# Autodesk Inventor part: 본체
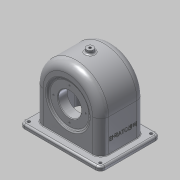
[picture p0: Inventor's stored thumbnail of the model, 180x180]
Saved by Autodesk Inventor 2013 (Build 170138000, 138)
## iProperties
Created: 2016-01
Part Number: 본체
Material: 알루미늄 6061
Document SubType Name: Modeling
Designer: dgall
Mass: 809.516 g
Surface Area: 999.209 cm^2
Volume: 298.714 cm^3
Density: 2.71 g/cm^3
Author: dgall
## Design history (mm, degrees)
sketch "스케치1"
  geometry: L1 (57, 0)-(57, -64); L2 (-57, 0)-(-57, -64); L3 (57, -64)-(-57, -64); A1 r 57 centre (0, 0) between (57, 0) and (-57, 0); 1 further point
  constraints: 6 end point, 2 parallel, 2 point on circle, 2 tangent, 1 centre point, 1 coincident, 1 perpendicular, 1 vertical
  dimensions: "d0" = 114 diameter of A1; "d2" = 64 vertical distance of L1.end point (0, 0)
extrude "돌출1" new body sketch "스케치1" distance "d3" = 77; taper "d4" = 0 deg
feature "쉘1" dims "d5" = 6
sketch "스케치2"
  geometry: L1 (-51, -64)-(-51, 0) reference; L2 (51, -64)-(-51, -64) reference; L3 (51, 0)-(51, -64) reference; A1 r 51 centre (0, 0) between (51, 0) and (-51, 0) reference
extrude "돌출2" cut sketch "스케치2" distance "d6" = 1; taper "d7" = 0 deg
sketch "스케치3"
  geometry: L1 (51, 0)-(51, 64) reference; L2 (-51, 64)-(51, 64) reference; L3 (-51, 64)-(-51, 0) reference; A1 r 51 centre (0, 0) between (-51, 0) and (51, 0) reference
extrude "돌출3" cut sketch "스케치3" distance "d8" = 1; taper "d9" = 0 deg
fillet "모깎기1" dims "d10" = 14, "d11" = 9
sketch "스케치4"
  geometry: L1 (-14, 14)-(-14, 63) reference; L2 (0, 0)-(86, 0) reference; L3 (100, 14)-(100, 63) reference; L4 (0, 77)-(86, 77) reference; L5 (-27, 90.5)-(113, 90.5); L6 (113, 90.5)-(113, -13.5); L7 (113, -13.5)-(-27, -13.5); L8 (-27, -13.5)-(-27, 90.5); L9 (-14, 38.5)-(100, 38.5); A1 r 14 centre (0, 63) between (0, 77) and (-14, 63) reference; A2 r 14 centre (0, 14) between (-14, 14) and (0, 0) reference; A3 r 14 centre (86, 14) between (86, 0) and (100, 14) reference; A4 r 14 centre (86, 63) between (100, 63) and (86, 77) reference; 1 further point
  constraints: 10 end point, 2 midpoint, 2 parallel, 1 horizontal, 1 perpendicular
  dimensions: "d12" = 140 distance between parallel lines of L6 L8; "d14" = 70 distance from line of point (43, 0) L8; "d15" = 104 distance between parallel lines of L7 L5; "d16" = 52 distance between parallel lines of L9 L5
extrude "돌출4" join sketch "스케치4" distance "d17" = 7; taper "d18" = 0 deg
fillet "모깎기2" dims "d19" = 8
sketch "스케치5"
  geometry: C1 r 2.5 at (-105, 82.5); C2 r 2.5 at (19, 82.5); C3 r 2.5 at (-105, -5.5); C4 r 2.5 at (19, -5.5); A1 r 8 centre (-105, 82.5) between (-105, 90.5) and (-113, 82.5) reference; A2 r 8 centre (-105, -5.5) between (-113, -5.5) and (-105, -13.5) reference; A3 r 8 centre (19, -5.5) between (19, -13.5) and (27, -5.5) reference; A4 r 8 centre (19, 82.5) between (27, 82.5) and (19, 90.5) reference; 1 further point
  constraints: 4 centre point, 4 coincident, 3 equal radius
  dimensions: "d20" = 5 diameter of C1
extrude "돌출5" cut sketch "스케치5" distance "d22" = 7; taper "d23" = 0 deg
sketch "스케치6"
  geometry: L1 (-62, 57)-(-62, 64) reference; L2 (62, 57)-(-62, 57) reference; L3 (62, 64)-(62, 57) reference; L4 (62, 64)-(-62, 64) reference; C1 r 31 at (0, 4); A1 r 43 centre (0, 0) between (-43, 0) and (43, 0) reference
  constraints: 1 centre point, 1 vertical alignment
  dimensions: "d24" = 60 distance from line of L4 C1.centre; "d25" = 62 diameter of C1
extrude "돌출6" join sketch "스케치6" distance "d26" = 10; taper "d27" = 0 deg
sketch "스케치7"
  geometry: C1 r 31 at (0, 0) reference; C2 r 20 at (0, 0); 1 further point
  constraints: 1 centre point, 1 coincident
  dimensions: "d28" = 40 diameter of C2
extrude "돌출7" cut sketch "스케치7" distance "d30" = 20.75; taper "d31" = 0 deg
sketch "스케치8"
  geometry: L1 (5, 42)-(5, 0) reference; L2 (5, 0)-(5, -64) reference; L3 (0, 0)-(0, 43) reference; L4 (0, -57)-(0, 0) reference; L5 (63, -64)-(14, -64) reference; L6 (0, -4)-(54.607, -4); L7 (5, -4)-(19, -4); L8 (19, -4)-(19, 24); L9 (19, 24)-(5, 35.747)
  constraints: 8 end point, 5 point on line, 1 parallel, 1 perpendicular
  dimensions: "d32" = 60 distance between parallel lines of L5 L6; "d33" = 28 distance from line of L6 L8.end; "d34" = 50 deg angle of L9 L8; "d36" = 14 distance between parallel lines of L8 L1
revolve "회전1" sketch "스케치8" stored, may be unused: angle "d37" = 90 deg
sketch "스케치11"
  geometry: L1 (5, 35.747)-(19, 24) reference; L2 (0, 33.416)-(3, 30.899); L3 (0, 0)-(0, 43) reference; L4 (0, -57)-(0, 0) reference; L5 (3, 30.899)-(3, -4); L6 (19, -32)-(19, 24) reference; L7 (19, -4)-(0, -4); L8 (0, 33.416)-(0, -4); L9 (3, -4)-(0, -4); L10 (63, -64)-(14, -64) reference
  constraints: 10 end point, 3 point on line, 2 collinear, 2 perpendicular, 1 midpoint, 1 parallel
  dimensions: "d45" = 5 distance between parallel lines of L1 L2; "d46" = 3 distance between parallel lines of L5 L3
revolve "회전3" sketch "스케치11" stored, may be unused: angle "d47" = 90 deg
sketch "스케치12"
  geometry: C1 r 34.899 at (0, 0) reference; C2 r 20 at (0, 0); 1 further point
  constraints: 1 centre point, 1 coincident
  dimensions: "d48" = 40 diameter of C2
extrude "돌출9" cut sketch "스케치12" distance "d50" = 20.75; taper "d51" = 0 deg
chamfer "모따기1" distance "d52" = 1; stored, may be unused: second distance "d53" = 2, angle "d54" = 45 deg
fillet "모깎기3" dims "d55" = 3
sketch "스케치13" dims "d56" = 48
  geometry: L1 (0, 0)-(0, -24); C1 r 21 at (0, 0) reference; C2 r 1.986 at (0, -24); C3 r 1.986 at (24, 0); C4 r 1.986 at (0, 24); C5 r 1.986 at (-24, 0); 1 further point
  constraints: 4 centre point, 2 coincident, 2 end point, 1 vertical, 1 vertical alignment, 11 other
  dimensions: "d60" = 360 deg dimension on L1.start C2.centre (derived)
hole "구멍1" sketch "스케치13" at (24, 0), (0, 24), (-24, 0), (0, -24) diameter "d62" = 2.459; stored, may be unused: countersink angle "d66" = 90 deg, drill point angle "d68" = 118 deg; dims "d63" = 6, "d64" = 4, "d65" = 2, "d67" = 8
sketch "스케치14" dims "d69" = 56
  geometry: L1 (0, 0)-(0, 28); C1 r 33.5 at (0, 0) reference; C2 r 2.705 at (0, 28); C3 r 2.705 at (-28, 0); C4 r 2.705 at (0, -28); C5 r 2.705 at (28, 0); 1 further point
  constraints: 4 centre point, 2 coincident, 2 end point, 1 vertical, 1 vertical alignment, 11 other
  dimensions: "d73" = 360 deg dimension on L1.start C2.centre (derived)
hole "구멍2" sketch "스케치14" at (0, 28), (28, 0), (0, -28), (-28, 0) diameter "d75" = 2.459; stored, may be unused: countersink angle "d79" = 90 deg, drill point angle "d81" = 118 deg; dims "d76" = 7, "d77" = 4, "d78" = 2, "d80" = 9
node "작업 평면2"
  node "작업 평면1"
sketch "스케치15"
  geometry: L1 (-43, 77)-(43, 77) reference; L2 (43, 0)-(-43, 0) reference; C1 r 6 at (0, 38.5); 2 further points
  constraints: 1 centre point, 1 midpoint, 1 vertical alignment
  dimensions: "d83" = 12 diameter of C1; "d85" = 38.5 distance from line of C1.centre L1
extrude "돌출10" join sketch "스케치15" stored distance "d86" = 20.75; taper "d87" = 0 deg
fillet "모깎기4" dims "d88" = 3
sketch "스케치16"
  geometry: C1 r 6 at (0, 0) reference; C2 r 1.707 at (0, 0); 1 further point
  constraints: 1 centre point, 1 coincident
hole "구멍3" sketch "스케치16" at (0, 0) diameter "d89" = 4.134; stored, may be unused: countersink angle "d93" = 90 deg, drill point angle "d95" = 118 deg; dims "d90" = 15, "d91" = 4, "d92" = 2, "d94" = 20
sketch "스케치17"
  geometry: L1 (5.347, -0.387)-(5.347, 49.387); L2 (5.347, 49.387)-(62.653, 49.387); L3 (62.653, 49.387)-(62.653, -0.387); L4 (62.653, -0.387)-(5.347, -0.387); L5 (34, -0.387)-(34, 49.387); L6 (62.653, 24.5)-(5.347, 24.5); L7 (0, -14)-(57, -14) reference; L8 (64, -19.5)-(64, 68.5) reference; 1 further point
  constraints: 5 midpoint, 4 end point, 2 other
  dimensions: "d96" = 38.5 distance between parallel lines of L6 L7; "d97" = 30 distance between parallel lines of L8 L5
extrude "돌출11" join sketch "스케치17" distance "d98" = 0.5; taper "d99" = 0 deg
fillet "모깎기5" dims "d100" = 1
node "솔리드1"
node "투영된 루프1"
other parameters: "d82" = 6
